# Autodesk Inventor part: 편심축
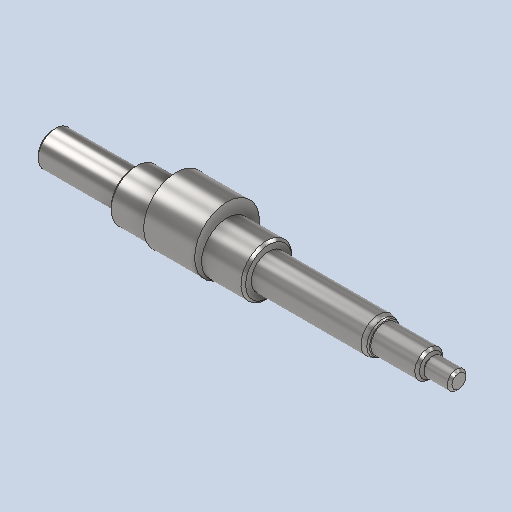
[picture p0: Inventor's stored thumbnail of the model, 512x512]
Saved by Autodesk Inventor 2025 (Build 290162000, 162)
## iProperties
Created: 2024-07
Part Number: 편심축
Material: 강철, 연강
Document SubType Name: Modeling
Designer: deana
Density: 7.86 g/cm^3
Appearance: 기본값
Author: jhkim
Sending System: Autodesk Inventor 2025
Preprocessor: ST-DEVELOPER v20
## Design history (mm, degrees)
feature "솔리드1"
node "솔리드2"
